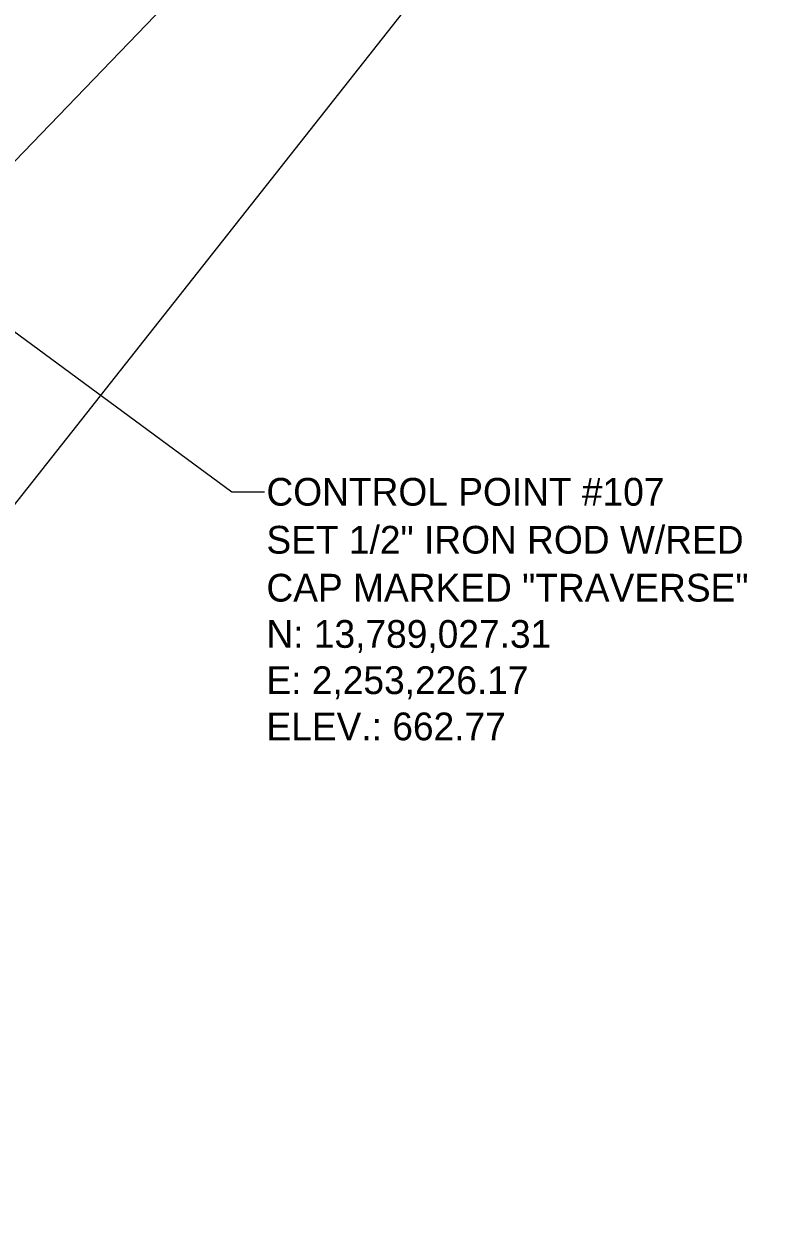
# Model space of a CAD drawing. Extents: x 2250985 to 2256614, y 13788357 to 13792478.
# Drawn here: x 2253234.3 to 2253266.9, y 13788983.2 to 13789034.9 of the extents above; entities that cross this region are included whole.
import ezdxf

# ---------------------------------------------------------------- set-up
doc = ezdxf.new("R2010")
doc.units = 0
for name, color, linetype in [('E_Control_Control Point See GPS AZM_CP_ANNO', 7, 'Continuous'), ('E_DTM_Grade Break_GB', 7, 'Continuous'), ('E_Structure_Fence_Wooden Fence_WDFN', 7, 'Continuous'), ('E_Utility_Water_Water Line_WL', 7, 'Continuous')]:
    doc.layers.add(name, color=color, linetype=linetype)

msp = doc.modelspace()

# ---------------------------------------------------------------- linework, layer by layer
at = {"layer": 'E_Control_Control Point See GPS AZM_CP_ANNO'}
msp.add_line((2253243.329, 13789014.674), (2253244.729, 13789014.674), dxfattribs=at)
msp.add_lwpolyline([(2253227.136, 13789026.598), (2253243.329, 13789014.674)], dxfattribs=at)
at = {"layer": 'E_DTM_Grade Break_GB'}
msp.add_spline([(2253199.79, 13789023.57), (2253231.26, 13789055.67), (2253305.08, 13789131.6), (2253378.64, 13789207.45), (2253453.2, 13789283.87)], degree=3, dxfattribs=at)
at = {"layer": 'E_Structure_Fence_Wooden Fence_WDFN'}
msp.add_lwpolyline([(2253221.88, 13788998.86), (2253252.59, 13789037.79), (2253318.96, 13789119.44), (2253334.24, 13789137.43), (2253391.06, 13789195.24), (2253466.27, 13789272.27), (2253486.74, 13789294.54)], dxfattribs=at)
at = {"layer": 'E_Utility_Water_Water Line_WL'}
msp.add_lwpolyline([(2253108.03, 13788872.99), (2253094.41, 13788884.22), (2253131.56, 13788921.3), (2253215.88, 13789010.21), (2253251.23, 13789046.95), (2253266.86, 13789062.3), (2253293.64, 13789088.87), (2253494.36, 13789292.49), (2253509.01, 13789307.27), (2253682.68, 13789482.53)], dxfattribs=at)

# ---------------------------------------------------------------- texts
at = {"layer": 'E_Control_Control Point See GPS AZM_CP_ANNO'}
for s, p in [('CONTROL POINT #107', (2253244.819, 13789014.074)), ('SET 1/2" IRON ROD W/RED ', (2253244.819, 13789012)), ('CAP MARKED "TRAVERSE"', (2253244.819, 13789009.926)), ('N: 13,789,027.31', (2253244.819, 13789007.926)), ('E: 2,253,226.17', (2253244.819, 13789005.926)), ('ELEV.: 662.77', (2253244.819, 13789003.926))]:
    msp.add_text(s, height=1.2, dxfattribs=at).set_placement(p)

doc.saveas('drawing.dxf')
